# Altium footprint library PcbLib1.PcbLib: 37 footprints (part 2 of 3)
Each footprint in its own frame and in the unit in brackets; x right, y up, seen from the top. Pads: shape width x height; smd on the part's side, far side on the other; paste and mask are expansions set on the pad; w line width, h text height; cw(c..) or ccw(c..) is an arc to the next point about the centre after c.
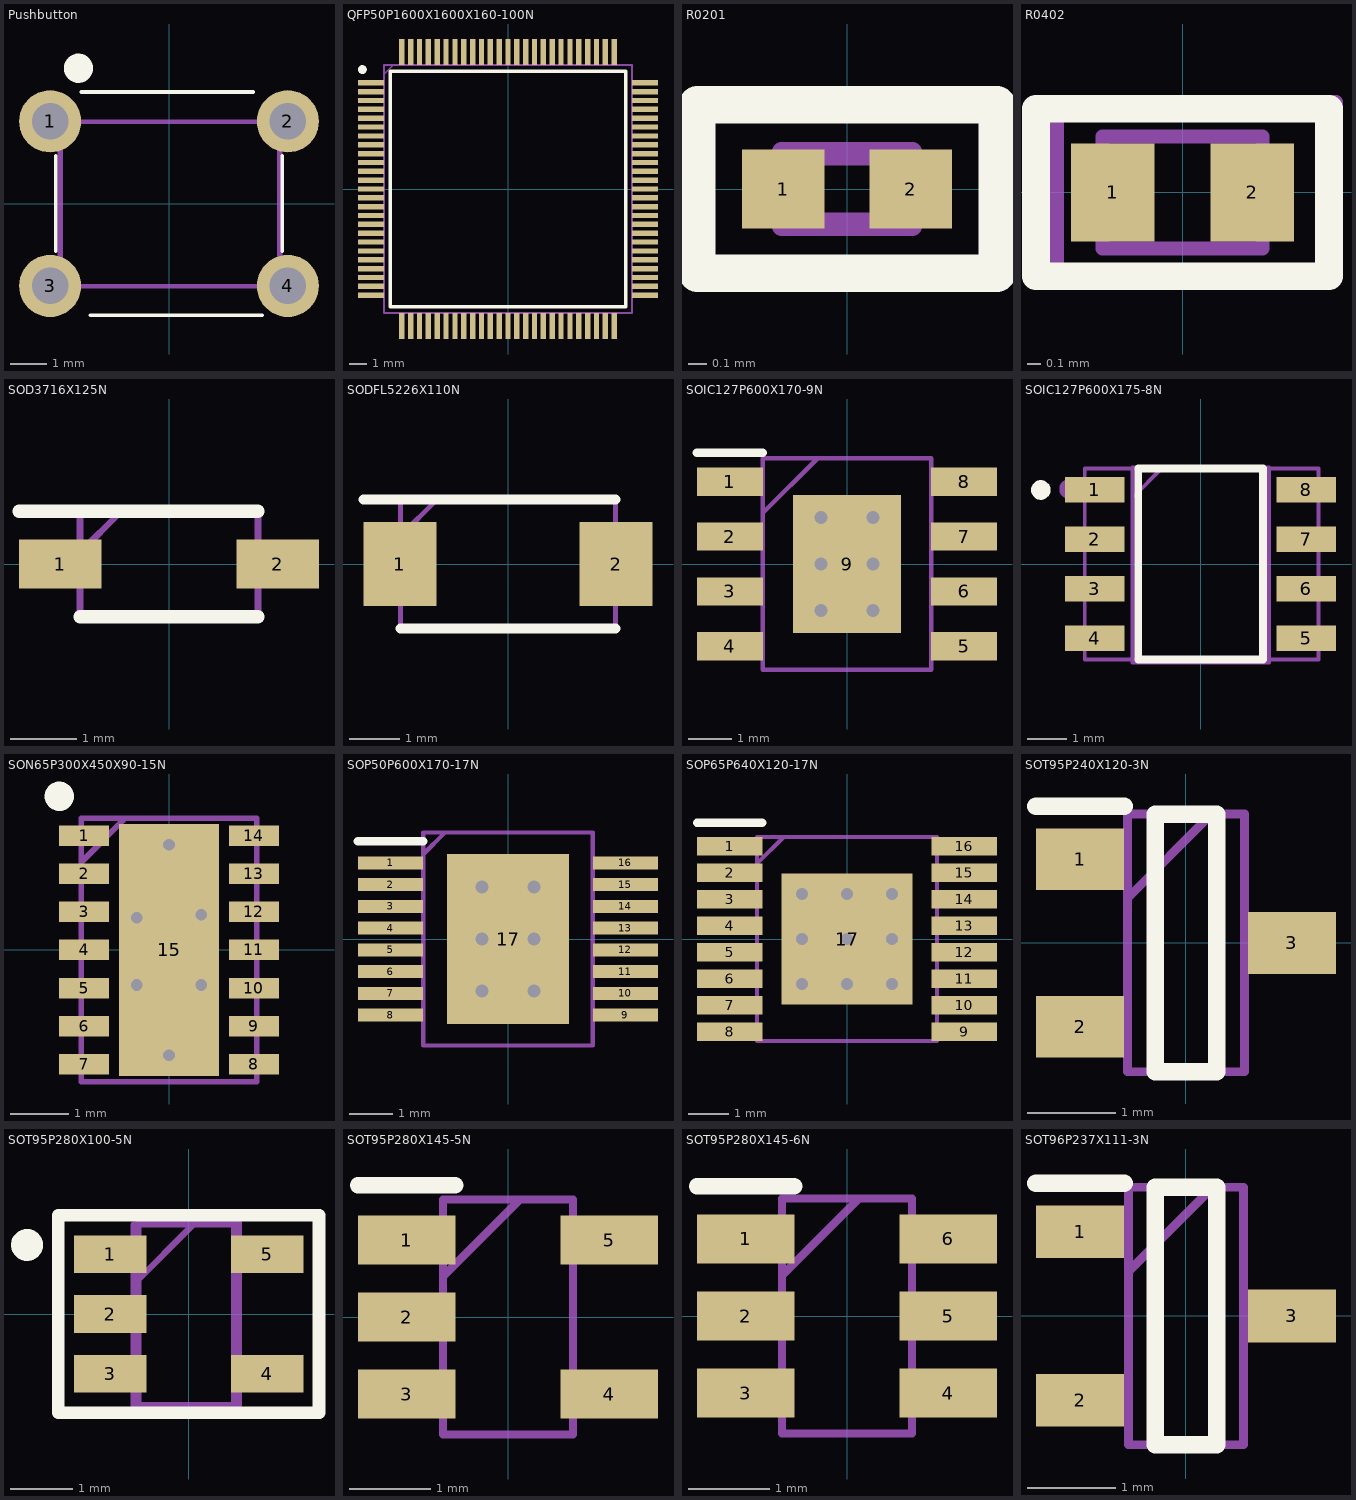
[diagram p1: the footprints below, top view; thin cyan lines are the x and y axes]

## Pushbutton [mm]
pads (4):
  round 1.7 hole 1: 1(-3.25,2.25) 2(3.25,2.25) 3(-3.25,-2.25) 4(3.25,-2.25)
Top Overlay:
  circle w0.4: c-2.475,3.7 r0.2
  lines w0.1: -3.1,-1.3 -3.1,1.3 ; -2.4,3.05 2.3,3.05 ; -2.15,-3.05 2.55,-3.05 ; 3.1,-1.3 3.1,1.3
Mechanical 13:
  circle w0.254: c-3.675,1.925 r0.135
  lines w0.1: -2.95,-2.275 -2.95,2.225 3.05,2.225 3.05,-2.275 -2.95,-2.275
  text ".Designator" at -2.55,-0.242 h0.7
Mechanical 29:
  circle w0.254: c-3.725,1.95 r0.135
  lines w0.1: -3,-2.25 -3,2.25 3,2.25 3,-2.25 -3,-2.25
  text ".Designator" at -2.6,-0.217 h0.7
Mechanical 30:
  text ".Comment" at -3.475,-1.6 h1
3D body "User Library-FSM6JHX(1-1977120-0).STEP": height 7, standoff -3.51, extent -3.9,-2.995 3.9,2.995

## QFP50P1600X1600X160-100N [mm]
pads (100):
  rect 1.475x0.3 smd: 1(-7.738,6) 2(-7.738,5.5) 3(-7.738,5) 4(-7.738,4.5) 5(-7.738,4) 6(-7.738,3.5) 7(-7.738,3) 8(-7.738,2.5) 9(-7.738,2) 10(-7.738,1.5) 11(-7.738,1) 12(-7.738,0.5) 13(-7.738,0) 14(-7.738,-0.5) 15(-7.738,-1) 16(-7.738,-1.5) 17(-7.738,-2) 18(-7.738,-2.5) 19(-7.738,-3) 20(-7.738,-3.5) 21(-7.738,-4) 22(-7.738,-4.5) 23(-7.738,-5) 24(-7.738,-5.5) 25(-7.738,-6) 51(7.738,-6) 52(7.738,-5.5) 53(7.738,-5) 54(7.738,-4.5) 55(7.738,-4) 56(7.738,-3.5) 57(7.738,-3) 58(7.738,-2.5) 59(7.738,-2) 60(7.738,-1.5) 61(7.738,-1) 62(7.738,-0.5) 63(7.738,0) 64(7.738,0.5) 65(7.738,1) 66(7.738,1.5) 67(7.738,2) 68(7.738,2.5) 69(7.738,3) 70(7.738,3.5) 71(7.738,4) 72(7.738,4.5) 73(7.738,5) 74(7.738,5.5) 75(7.738,6)
  rect 0.3x1.475 smd: 26(-6,-7.738) 27(-5.5,-7.738) 28(-5,-7.738) 29(-4.5,-7.738) 30(-4,-7.738) 31(-3.5,-7.738) 32(-3,-7.738) 33(-2.5,-7.738) 34(-2,-7.738) 35(-1.5,-7.738) 36(-1,-7.738) 37(-0.5,-7.738) 38(0,-7.738) 39(0.5,-7.738) 40(1,-7.738) 41(1.5,-7.738) 42(2,-7.738) 43(2.5,-7.738) 44(3,-7.738) 45(3.5,-7.738) 46(4,-7.738) 47(4.5,-7.738) 48(5,-7.738) 49(5.5,-7.738) 50(6,-7.738) 76(6,7.738) 77(5.5,7.738) 78(5,7.738) 79(4.5,7.738) 80(4,7.738) 81(3.5,7.738) 82(3,7.738) 83(2.5,7.738) 84(2,7.738) 85(1.5,7.738) 86(1,7.738) 87(0.5,7.738) 88(0,7.738) 89(-0.5,7.738) 90(-1,7.738) 91(-1.5,7.738) 92(-2,7.738) 93(-2.5,7.738) 94(-3,7.738) 95(-3.5,7.738) 96(-4,7.738) 97(-4.5,7.738) 98(-5,7.738) 99(-5.5,7.738) 100(-6,7.738)
Top Overlay:
  circle w0.25: c-8.225,6.75 r0.125
  lines w0.2: -6.65,-6.65 -6.65,6.65 6.65,6.65 6.65,-6.65 -6.65,-6.65
Mechanical 13:
  lines w0.1: -7,6.5 -6.5,7 ; -7,-7 -7,7 7,7 7,-7 -7,-7
  text ".Designator" at -3.857,-0.356 h1
3D body "TMS5700332BPZQQ1.stp": height 1.6, standoff 0, extent -8,-8 8,8

## R0201 [mm]
pads (2):
  rect 0.44x0.42 smd: 1(-0.34,0) 2(0.34,0)
Top Overlay:
  lines w0.2: -0.8,-0.45 -0.8,0.45 0.8,0.45 0.8,-0.45 -0.8,-0.45
Mechanical 13:
  lines w0.1: -0.35,-0.175 -0.35,0.175 0.35,0.175 0.35,-0.175 -0.35,-0.175
  text ".Designator" at -0.65,-0.183 h0.5
Mechanical 29:
  lines w0.1: -0.35,-0.2 0.35,-0.2 0.35,0.2 -0.35,0.2 -0.35,-0.2
  text ".Designator" at -0.25,0 h0.3
Mechanical 30:
  text ".Comment" at -1.225,-0.7 h0.5
3D body "RC0201FR-0712KL.stp": height 0.26, standoff 0, extent -0.3,-0.15 0.3,0.15

## R0402 [mm]
pads (2):
  rect 0.6x0.7 smd: 1(-0.5,0) 2(0.5,0)
Top Overlay:
  lines w0.2: -1.05,-0.6 -1.05,0.6 1.05,0.6 1.05,-0.6 -1.05,-0.6
Mechanical 13:
  lines w0.1: -0.9,-0.6 -0.9,0.65 1.1,0.65 1.1,-0.6 -0.9,-0.6
  text ".Designator" at -1.307,-0.431 h1
Mechanical 29:
  lines w0.1: -0.575,-0.4 0.575,-0.4 0.575,0.4 -0.575,0.4 -0.575,-0.4
  text "'.Designator'" at -0.675,-0.117 h0.4
Mechanical 30:
  text ".Comment" at -1.425,-0.825 h0.5
3D body "RC0402N_YAG.step": height 0.51, standoff 0.01, extent -0.533,-0.35 0.533,0.361

## SOD3716X125N [mm]
pads (2):
  rect 1.25x0.75 smd: 1(-1.65,0) 2(1.65,0)
Top Overlay:
  lines w0.2: -2.275,0.8 1.35,0.8 ; -1.35,-0.8 1.35,-0.8
Mechanical 13:
  lines w0.1: -1.35,0.175 -0.725,0.8 ; -1.35,-0.8 1.35,-0.8 1.35,0.8 -1.35,0.8 -1.35,-0.8
  text ".Designator" at -1.963,-0.528 h1.1
3D body "1N5819HW-7-F.stp": height 1.25, standoff 0.06, extent -1.35,-0.8 1.35,0.8

## SODFL5226X110N [mm]
pads (2):
  rect 1.46x1.67 smd: 1(-2.15,0) 2(2.15,0)
Top Overlay:
  lines w0.2: -2.88,1.288 2.138,1.288 ; -2.138,-1.288 2.138,-1.288
Mechanical 13:
  lines w0.1: -2.138,0.558 -1.408,1.288 ; -2.138,-1.288 2.138,-1.288 2.138,1.288 -2.138,1.288 -2.138,-1.288
  text ".Designator" at -2.063,-0.428 h1.1
3D body "STPS2L25AFN.stp": height 1.1, standoff 0, extent -2.588,-1.288 2.588,1.288

## SOIC127P600X170-9N [mm]
pads (9):
  rect 1.525x0.65 smd: 1(-2.712,1.905) 2(-2.712,0.635) 3(-2.712,-0.635) 4(-2.712,-1.905) 5(2.712,-1.905) 6(2.712,-0.635) 7(2.712,0.635) 8(2.712,1.905)
  rect 2.51x3.2 smd paste-4: 9(0,0)
via -0.6,1.075 diameter 0.7 hole 0.3
via 0.6,1.075 diameter 0.7 hole 0.3
via -0.6,0 diameter 0.7 hole 0.3
via -0.6,-1.075 diameter 0.7 hole 0.3
via 0.6,0 diameter 0.7 hole 0.3
via 0.6,-1.075 diameter 0.7 hole 0.3
Top Overlay:
  lines w0.2: -3.475,2.58 -1.95,2.58
Top Paste:
  rectangle: 0.15,-1.55 1.05,-0.65
  rectangle: 0.15,-0.45 1.05,0.45
  rectangle: 0.15,0.65 1.05,1.55
  rectangle: -1.05,-1.55 -0.15,-0.65
  rectangle: -1.05,-0.45 -0.15,0.45
  rectangle: -1.05,0.65 -0.15,1.55
Mechanical 13:
  lines w0.1: -1.95,1.18 -0.68,2.45 ; -1.95,-2.45 1.95,-2.45 1.95,2.45 -1.95,2.45 -1.95,-2.45
  text ".Designator" at -2.363,-0.653 h1.1
3D body "A7985ATR.stp": height 1.7, standoff 0, extent -3,-2.45 3,2.45

## SOIC127P600X175-8N [mm]
pads (8):
  rect 1.525x0.65 smd: 1(-2.712,1.905) 2(-2.712,0.635) 3(-2.712,-0.635) 4(-2.712,-1.905) 5(2.712,-1.905) 6(2.712,-0.635) 7(2.712,0.635) 8(2.712,1.905)
Top Overlay:
  circle w0.254: c-4.1,1.9 r0.125
  lines w0.2: -1.6,-2.45 -1.6,2.45 1.6,2.45 1.6,-2.45 -1.6,-2.45
Mechanical 13:
  lines w0.1: -1.725,1.725 -0.975,2.475 ; -1.75,-2.525 1.75,-2.525 1.75,2.475 -1.75,2.475 -1.75,-2.525
  text ".Designator" at -1.938,-0.378 h1.1
Mechanical 29:
  circle w0.254: c-3.375,1.925 r0.125
  lines w0.1: -2.975,-2.45 -2.975,2.45 3.025,2.45 3.025,-2.45 -2.975,-2.45
  text ".Designator" at -3,-0.467 h1
Mechanical 30:
  text ".Comment" at -3,-0.45 h1
3D body "NE555DR.stp": height 1.75, standoff 0, extent -3,-2.45 3,2.45

## SON65P300X450X90-15N [mm]
pads (15):
  rect 0.85x0.35 smd: 1(-1.45,1.95) 2(-1.45,1.3) 3(-1.45,0.65) 4(-1.45,0) 5(-1.45,-0.65) 6(-1.45,-1.3) 7(-1.45,-1.95) 8(1.45,-1.95) 9(1.45,-1.3) 10(1.45,-0.65) 11(1.45,0) 12(1.45,0.65) 13(1.45,1.3) 14(1.45,1.95)
  rect 1.7x4.3 smd paste-5: 15(0,0)
via 0,1.8 diameter 0.5 hole 0.2
via -0.55,0.55 diameter 0.5 hole 0.2
via -0.55,-0.6 diameter 0.5 hole 0.2
via 0,-1.8 diameter 0.5 hole 0.2
via 0.55,-0.6 diameter 0.5 hole 0.2
via 0.55,0.6 diameter 0.5 hole 0.2
Top Overlay:
  circle w0.25: c-1.875,2.625 r0.125
Top Paste:
  rectangle: -0.55,-2.1 0.55,-1
  rectangle: -0.55,-0.55 0.55,0.55
  rectangle: -0.55,1 0.55,2.1
Mechanical 13:
  lines w0.1: -1.5,1.5 -0.75,2.25 ; -1.5,-2.25 1.5,-2.25 1.5,2.25 -1.5,2.25 -1.5,-2.25
  text ".Designator" at -1.988,-0.378 h1.1
3D body "TCAN1043DMTRQ1.stp": height 0.9, standoff 0, extent -1.55,-2.25 1.55,2.25

## SOP50P600X170-17N [mm]
pads (17):
  rect 1.5x0.3 smd: 1(-2.7,1.75) 2(-2.7,1.25) 3(-2.7,0.75) 4(-2.7,0.25) 5(-2.7,-0.25) 6(-2.7,-0.75) 7(-2.7,-1.25) 8(-2.7,-1.75) 9(2.7,-1.75) 10(2.7,-1.25) 11(2.7,-0.75) 12(2.7,-0.25) 13(2.7,0.25) 14(2.7,0.75) 15(2.7,1.25) 16(2.7,1.75)
  rect 2.8x3.91 smd paste-4: 17(0,0)
via 0.6,-1.2 diameter 0.7 hole 0.3
via -0.6,-1.2 diameter 0.7 hole 0.3
via -0.6,0 diameter 0.7 hole 0.3
via -0.6,1.2 diameter 0.7 hole 0.3
via 0.6,1.2 diameter 0.7 hole 0.3
via 0.6,0 diameter 0.7 hole 0.3
Top Overlay:
  lines w0.2: -3.45,2.25 -1.95,2.25
Top Paste:
  rectangle: -1.25,-0.55 -0.15,0.55
  rectangle: 0.15,-0.55 1.25,0.55
  rectangle: 0.15,-1.85 1.25,-0.75
  rectangle: -1.25,-1.85 -0.15,-0.75
  rectangle: 0.15,0.75 1.25,1.85
  rectangle: -1.25,0.75 -0.15,1.85
Mechanical 13:
  lines w0.1: -1.95,1.95 -1.45,2.45 ; -1.95,-2.45 -1.95,2.45 1.95,2.45 1.95,-2.45 -1.95,-2.45
  text ".Designator" at -2.163,-0.653 h1.1
3D body "VND7020AJTR.stp": height 1.7, standoff 0, extent -3,-2.45 3,2.45

## SOP65P640X120-17N [mm]
pads (17):
  rect 1.6x0.45 smd: 1(-2.875,2.275) 2(-2.875,1.625) 3(-2.875,0.975) 4(-2.875,0.325) 5(-2.875,-0.325) 6(-2.875,-0.975) 7(-2.875,-1.625) 8(-2.875,-2.275) 9(2.875,-2.275) 10(2.875,-1.625) 11(2.875,-0.975) 12(2.875,-0.325) 13(2.875,0.325) 14(2.875,0.975) 15(2.875,1.625) 16(2.875,2.275)
  rect 3.2x3.2 smd paste-3: 17(0,0)
via 0,0 diameter 0.7 hole 0.3
via -1.1,0 diameter 0.7 hole 0.3
via 1.1,0 diameter 0.7 hole 0.3
via -1.1,1.1 diameter 0.7 hole 0.3
via -1.1,-1.1 diameter 0.7 hole 0.3
via 0,-1.1 diameter 0.7 hole 0.3
via 0,1.1 diameter 0.7 hole 0.3
via 1.1,-1.1 diameter 0.7 hole 0.3
via 1.1,1.1 diameter 0.7 hole 0.3
Top Overlay:
  lines w0.2: -3.675,2.85 -2.075,2.85
Top Paste:
  rectangle: -1.525,0.625 -0.625,1.525
  rectangle: -1.525,-0.45 -0.625,0.45
  rectangle: -1.525,-1.525 -0.625,-0.625
  rectangle: -0.45,0.625 0.45,1.525
  rectangle: -0.45,-0.45 0.45,0.45
  rectangle: -0.45,-1.525 0.45,-0.625
  rectangle: 0.625,0.625 1.525,1.525
  rectangle: 0.625,-0.45 1.525,0.45
  rectangle: 0.625,-1.525 1.525,-0.625
Mechanical 13:
  lines w0.1: -2.2,1.85 -1.55,2.5 ; -2.2,-2.5 -2.2,2.5 2.2,2.5 2.2,-2.5 -2.2,-2.5
  text ".Designator" at -2.213,-0.703 h1.1
3D body "A7987TR.stp": height 1.2, standoff 0, extent -3.2,-2.5 3.2,2.5

## SOT95P240X120-3N [mm]
pads (3):
  rect 1x0.7 smd: 1(-1.2,0.95) 2(-1.2,-0.95) 3(1.2,0)
Top Overlay:
  lines w0.2: -1.7,1.55 -0.7,1.55 ; -0.35,-1.46 -0.35,1.46 0.35,1.46 0.35,-1.46 -0.35,-1.46
Mechanical 13:
  lines w0.1: -0.662,0.51 0.288,1.46 ; -0.662,-1.46 -0.662,1.46 0.662,1.46 0.662,-1.46 -0.662,-1.46
  text ".Designator" at -1.888,-0.428 h1.1
3D body "MMBT5401.stp": height 1.2, standoff 0, extent -1.2,-1.46 1.2,1.46

## SOT95P280X100-5N [mm]
pads (5):
  rect 1.15x0.6 smd: 1(-1.25,0.95) 2(-1.25,0) 3(-1.25,-0.95) 4(1.25,-0.95) 5(1.25,0.95)
Top Overlay:
  circle w0.254: c-2.575,1.1 r0.127
  lines w0.2: -2.075,-1.575 -2.075,1.575 2.075,1.575 2.075,-1.575 -2.075,-1.575
Mechanical 13:
  lines w0.1: -0.875,0.475 0.075,1.425 ; -0.875,-1.475 0.725,-1.475 0.725,1.425 -0.875,1.425 -0.875,-1.475
  text ".Designator" at -2.088,-0.253 h1.1
Mechanical 29:
  circle w0.254: c-1.25,1 r0.056
  lines w0.1: -0.8,-1.45 -0.8,1.45 0.8,1.45 0.8,-1.45 -0.8,-1.45
  text ".Designator" at -1.275,-0.408 h0.8
Mechanical 30:
  text ".Comment" at -1.775,-1.7 h1
3D body "AD8538AUJZ-REEL7.stp": height 1, standoff 0, extent -1.4,-1.45 1.4,1.45

## SOT95P280X145-5N [mm]
pads (5):
  rect 1.2x0.6 smd: 1(-1.25,0.95) 2(-1.25,0) 3(-1.25,-0.95) 4(1.25,-0.95) 5(1.25,0.95)
Top Overlay:
  lines w0.2: -1.85,1.625 -0.65,1.625
Mechanical 13:
  lines w0.1: -0.8,0.5 0.15,1.45 ; -0.8,-1.45 0.8,-1.45 0.8,1.45 -0.8,1.45 -0.8,-1.45
  text ".Designator" at -2.013,-0.228 h1.1
3D body "INA193AQDBVRQ1.stp": height 1.2, standoff 0, extent -1.4,-1.45 1.4,1.45

## SOT95P280X145-6N [mm]
pads (6):
  rect 1.2x0.6 smd: 1(-1.25,0.95) 2(-1.25,0) 3(-1.25,-0.95) 4(1.25,-0.95) 5(1.25,0) 6(1.25,0.95)
Top Overlay:
  lines w0.2: -1.85,1.6 -0.65,1.6
Mechanical 13:
  lines w0.1: -0.8,0.5 0.15,1.45 ; -0.8,-1.45 0.8,-1.45 0.8,1.45 -0.8,1.45 -0.8,-1.45
  text ".Designator" at -1.463,-0.603 h1.1
3D body "REF3430TIDBVR.stp": height 1.2, standoff 0, extent -1.4,-1.45 1.4,1.45

## SOT96P237X111-3N [mm]
pads (3):
  rect 1x0.6 smd: 1(-1.2,0.955) 2(-1.2,-0.955) 3(1.2,0)
Top Overlay:
  lines w0.2: -1.7,1.505 -0.7,1.505 ; -0.35,-1.46 0.35,-1.46 0.35,1.46 -0.35,1.46 -0.35,-1.46
Mechanical 13:
  lines w0.1: -0.65,0.505 0.305,1.46 ; -0.65,-1.46 0.65,-1.46 0.65,1.46 -0.65,1.46 -0.65,-1.46
  text ".Designator" at -1.313,-0.553 h1.1
3D body "BZX84C12LT1G.stp": height 1.11, standoff 0, extent -1.185,-1.46 1.185,1.46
